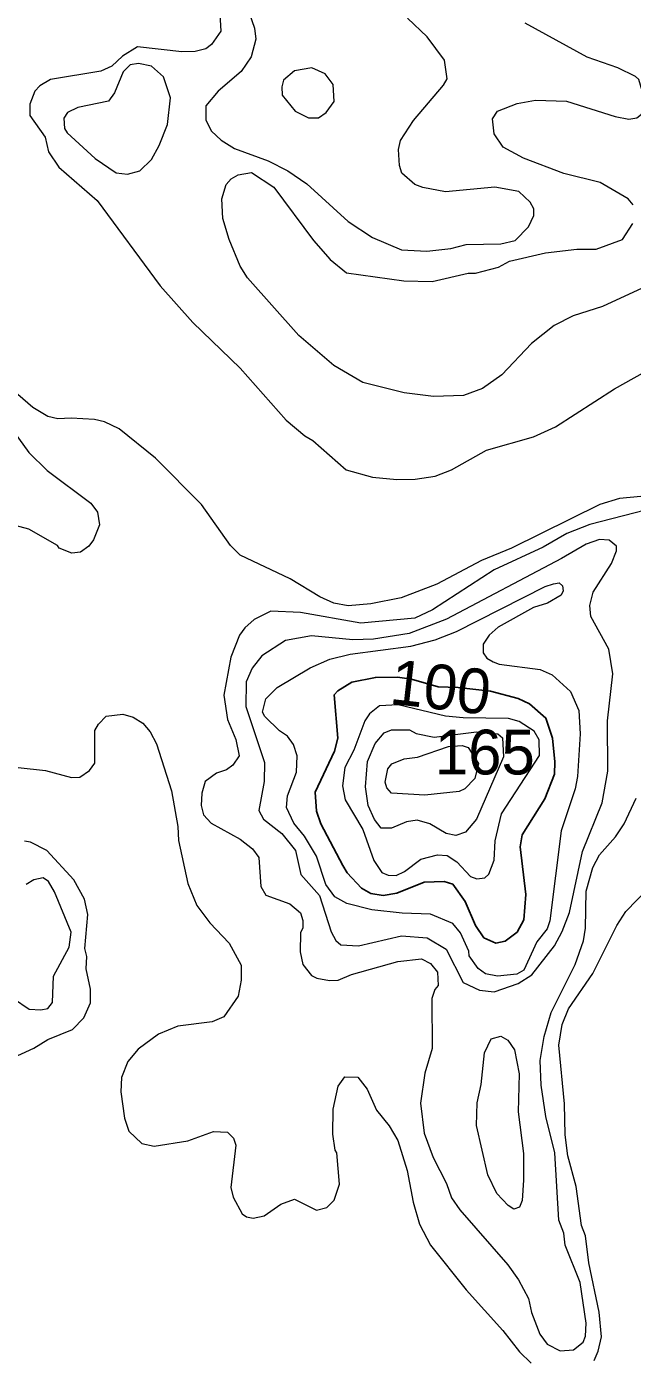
# Model space of a CAD drawing. Extents: x 673.6 to 698.9, y 7012 to 7040.1.
# Drawn here: x 690.749 to 691.831, y 7021.918 to 7024.299 of the extents above; entities that cross this region are included whole.
import ezdxf
from ezdxf.enums import TextEntityAlignment as Align

# ---------------------------------------------------------------- set-up
doc = ezdxf.new("R2010")
doc.units = 0
doc.header["$LTSCALE"] = 0.032
doc.layers.add('1', color=7, linetype='Continuous', lineweight=25)
doc.layers.add('2', color=7, linetype='Continuous', lineweight=13)
doc.layers.add('21', color=7, linetype='Continuous')
doc.layers.add('61', color=7, linetype='Continuous')

msp = doc.modelspace()

# ---------------------------------------------------------------- linework, layer by layer
at = {"layer": '1'}
msp.add_lwpolyline([(691.4117, 7023.1369), (691.4368, 7023.1335), (691.4845, 7023.1197), (691.5202, 7023.1186), (691.5777, 7023.1117), (691.6272, 7023.0987), (691.6472, 7023.0893), (691.6766, 7023.0637), (691.6883, 7023.0278), (691.6929, 7022.9856), (691.692, 7022.9635), (691.6748, 7022.9194), (691.6345, 7022.855), (691.6306, 7022.8336), (691.6411, 7022.7487), (691.6371, 7022.7035), (691.6254, 7022.6812), (691.6042, 7022.6653), (691.5875, 7022.6616), (691.5661, 7022.6708), (691.5507, 7022.693), (691.5325, 7022.7358), (691.5105, 7022.7669), (691.4953, 7022.7715), (691.4591, 7022.7707), (691.4103, 7022.7507), (691.3861, 7022.7469), (691.3639, 7022.7504), (691.3475, 7022.76), (691.3216, 7022.7872), (691.3138, 7022.8001), (691.2747, 7022.875), (691.2671, 7022.8973), (691.2648, 7022.9314), (691.2993, 7023.0049), (691.305, 7023.028), (691.2987, 7023.105), (691.3049, 7023.1123), (691.3301, 7023.1282), (691.3721, 7023.1364)], close=True, dxfattribs=at)
at = {"layer": '2'}
for points in [[(691.0939, 7024.3325), (691.0963, 7024.2913), (691.0794, 7024.2674), (691.0691, 7024.2598), (691.0504, 7024.2548), (691.0266, 7024.254), (690.947, 7024.263), (690.9207, 7024.2465), (690.9011, 7024.2287), (690.8817, 7024.2197), (690.792, 7024.2045), (690.7725, 7024.1934), (690.7636, 7024.1841), (690.7549, 7024.1608), (690.7547, 7024.1406), (690.7822, 7024.1018), (690.788, 7024.0755), (690.8068, 7024.048), (690.8753, 7023.9885), (690.9875, 7023.836), (691.0462, 7023.7708), (691.1306, 7023.6888), (691.2125, 7023.5963), (691.2459, 7023.5682), (691.2607, 7023.5595), (691.3201, 7023.5075), (691.3671, 7023.4944), (691.4106, 7023.4898), (691.4435, 7023.4904), (691.4788, 7023.4958), (691.5081, 7023.5074), (691.5709, 7023.5424), (691.6547, 7023.5665), (691.694, 7023.584), (691.799, 7023.6523), (691.9898, 7023.7589)], [(691.1469, 7024.3241), (691.1563, 7024.2967), (691.1588, 7024.277), (691.1502, 7024.2452), (691.1327, 7024.2189), (691.0912, 7024.1839), (691.0693, 7024.1577), (691.0693, 7024.132), (691.0793, 7024.1124), (691.0964, 7024.0965), (691.1207, 7024.0816), (691.1807, 7024.0597), (691.216, 7024.0413), (691.25, 7024.0181), (691.3234, 7023.9513), (691.3672, 7023.9222), (691.4189, 7023.9006), (691.4639, 7023.8982), (691.5069, 7023.903), (691.5342, 7023.9097), (691.5963, 7023.9113), (691.622, 7023.9169), (691.6459, 7023.9414), (691.6551, 7023.9618), (691.6551, 7023.9734), (691.6487, 7023.9858), (691.6284, 7024.0048), (691.5858, 7024.0123), (691.4975, 7024.0042), (691.457, 7024.0117), (691.4424, 7024.0174), (691.4196, 7024.0373), (691.4152, 7024.051), (691.4136, 7024.0794), (691.4171, 7024.0959), (691.4402, 7024.1314), (691.4939, 7024.1945), (691.5004, 7024.206), (691.4957, 7024.2392), (691.4648, 7024.2808), (691.4293, 7024.3145)], [(691.5841, 7024.1076), (691.5813, 7024.1345), (691.5905, 7024.1481), (691.6257, 7024.1619), (691.6584, 7024.1676), (691.7136, 7024.1661), (691.8002, 7024.1385), (691.8248, 7024.1341), (691.8389, 7024.1364), (691.8477, 7024.1426), (691.8548, 7024.1645), (691.8425, 7024.2046), (691.8367, 7024.2104), (691.8051, 7024.2259), (691.7506, 7024.2449), (691.6397, 7024.3053)], [(691.8236, 7023.9917), (691.7738, 7024.0205), (691.7085, 7024.0368), (691.637, 7024.0641), (691.6003, 7024.0841), (691.5841, 7024.1076)], [(691.8644, 7023.8393), (691.7777, 7023.7993), (691.7255, 7023.7822), (691.6914, 7023.765), (691.6513, 7023.7332), (691.5981, 7023.6768), (691.5635, 7023.6526), (691.5297, 7023.6401), (691.4757, 7023.6386), (691.4238, 7023.645), (691.35, 7023.6633), (691.2981, 7023.6935), (691.2353, 7023.7476), (691.1437, 7023.8506), (691.1307, 7023.8713), (691.1109, 7023.9188), (691.0997, 7023.9562), (691.098, 7023.9918), (691.1055, 7024.0172), (691.1148, 7024.0274), (691.1271, 7024.0345), (691.1509, 7024.0384), (691.1908, 7024.0123), (691.2614, 7023.9173), (691.2912, 7023.8832), (691.3206, 7023.8593), (691.4229, 7023.8451), (691.4734, 7023.844), (691.5377, 7023.8586), (691.5508, 7023.8589), (691.5923, 7023.8694), (691.612, 7023.88), (691.6762, 7023.8948), (691.7321, 7023.9014), (691.7667, 7023.9017), (691.8137, 7023.9191), (691.8319, 7023.9474)], [(691.8325, 7023.9811), (691.8236, 7023.9917)], [(691.5615, 7023.3451), (691.4819, 7023.3029), (691.4182, 7023.2785), (691.3639, 7023.2678), (691.3237, 7023.2646), (691.2982, 7023.2692), (691.273, 7023.2801), (691.2202, 7023.3127), (691.1304, 7023.3546), (691.1131, 7023.3724), (691.0616, 7023.4456), (690.9796, 7023.5283), (690.9142, 7023.5807), (690.8883, 7023.593), (690.8702, 7023.5972), (690.8288, 7023.5999), (690.8051, 7023.5983), (690.7868, 7023.6027), (690.7605, 7023.6186), (690.7333, 7023.6421)], [(690.6972, 7023.615), (690.7533, 7023.5385), (690.7856, 7023.5063), (690.8637, 7023.4478), (690.8758, 7023.4315), (690.8793, 7023.409), (690.8685, 7023.3824), (690.8603, 7023.3712), (690.8455, 7023.3603), (690.83, 7023.3583), (690.8075, 7023.3674), (690.8044, 7023.3722), (690.7529, 7023.401), (690.7158, 7023.4115)], [(691.8728, 7023.467), (691.8463, 7023.4599), (691.8081, 7023.456), (691.7732, 7023.4452), (691.6154, 7023.3672), (691.5615, 7023.3451)], [(691.8549, 7023.4353), (691.7551, 7023.4099), (691.7143, 7023.3936), (691.672, 7023.3691), (691.5842, 7023.3284), (691.474, 7023.257), (691.4428, 7023.2424), (691.3459, 7023.2334), (691.2386, 7023.2523), (691.1853, 7023.2548), (691.1559, 7023.2401), (691.1387, 7023.2248), (691.1293, 7023.2119), (691.1139, 7023.1726), (691.1014, 7023.1047), (691.1078, 7023.0612), (691.1229, 7023.0257), (691.129, 7022.9963), (691.1177, 7022.9796), (691.1064, 7022.9715), (691.0881, 7022.9654), (691.0682, 7022.9506), (691.0619, 7022.9293), (691.0611, 7022.9076)], [(690.7341, 7022.9753), (690.7831, 7022.9703), (690.8294, 7022.9573), (690.8445, 7022.9581), (690.8613, 7022.9703), (690.8711, 7022.9832), (690.8712, 7023.0415), (690.8774, 7023.0529), (690.891, 7023.0672), (690.9209, 7023.0705), (690.9396, 7023.0651), (690.9569, 7023.0547), (690.97, 7023.0391), (690.9813, 7023.018), (691.0078, 7022.9336), (691.019, 7022.8701), (691.0205, 7022.845), (691.0374, 7022.7679), (691.053, 7022.7288), (691.0767, 7022.6976), (691.1109, 7022.6617), (691.1324, 7022.6221), (691.1325, 7022.5954), (691.1273, 7022.5671), (691.1013, 7022.5301)], [(691.0611, 7022.9076), (691.0652, 7022.8909), (691.0791, 7022.876), (691.1306, 7022.8473), (691.1527, 7022.8301), (691.1639, 7022.8148)], [(691.4123, 7022.6286), (691.4546, 7022.6334), (691.4707, 7022.6254), (691.483, 7022.6099), (691.4842, 7022.5861), (691.4784, 7022.5789), (691.4728, 7022.5628), (691.4736, 7022.4731), (691.4604, 7022.4294), (691.453, 7022.3757), (691.4593, 7022.322), (691.4752, 7022.2786), (691.4991, 7022.2321), (691.5084, 7022.2063), (691.5233, 7022.1848), (691.6089, 7022.0865), (691.628, 7022.0599), (691.6454, 7022.0267), (691.651, 7022.0016), (691.6658, 7021.9631), (691.6791, 7021.9451), (691.7023, 7021.9329), (691.7258, 7021.935), (691.7435, 7021.9486), (691.7473, 7021.9596), (691.7489, 7021.9827), (691.7377, 7022.0554), (691.7112, 7022.122), (691.7085, 7022.1434), (691.6996, 7022.1664), (691.6929, 7022.2871), (691.6766, 7022.3521), (691.6684, 7022.408), (691.6667, 7022.4518), (691.6734, 7022.4946), (691.6863, 7022.5378), (691.729, 7022.6233), (691.7438, 7022.666), (691.7472, 7022.6886), (691.7489, 7022.7542), (691.7606, 7022.7969), (691.7726, 7022.8192), (691.8012, 7022.8518), (691.8167, 7022.8749), (691.838, 7022.9206)], [(690.7178, 7022.4536), (690.7623, 7022.4739), (690.7871, 7022.4895), (690.8311, 7022.5074), (690.8516, 7022.5282), (690.8631, 7022.5551), (690.863, 7022.5792), (690.8555, 7022.6158), (690.8565, 7022.6379), (690.8532, 7022.6521), (690.8588, 7022.713), (690.8523, 7022.7403), (690.8334, 7022.7748), (690.7852, 7022.8272), (690.7561, 7022.8422), (690.7456, 7022.8437)], [(691.1639, 7022.8148), (691.1676, 7022.7629), (691.1767, 7022.7473), (691.2196, 7022.7321), (691.2383, 7022.7159), (691.2426, 7022.7021), (691.2427, 7022.6888), (691.2386, 7022.6801), (691.2378, 7022.6463), (691.2427, 7022.6237), (691.2582, 7022.604), (691.2677, 7022.5989), (691.29, 7022.5949), (691.3059, 7022.5957), (691.3294, 7022.6054), (691.4123, 7022.6286)], [(691.7629, 7021.9158), (691.7704, 7021.9324), (691.7758, 7021.9581), (691.7718, 7022.0023), (691.7533, 7022.0906), (691.7472, 7022.1388), (691.7406, 7022.1572), (691.7308, 7022.2268), (691.7161, 7022.2814), (691.7111, 7022.3188), (691.7102, 7022.3745), (691.6996, 7022.4794), (691.7061, 7022.5165), (691.7173, 7022.5441), (691.7603, 7022.6071), (691.8032, 7022.6929), (691.8193, 7022.7179), (691.9229, 7022.825)], [(690.7259, 7022.5626), (690.7536, 7022.5436), (690.7746, 7022.5423), (690.7873, 7022.545), (690.7954, 7022.5553), (690.7973, 7022.6027), (690.8251, 7022.6545), (690.8285, 7022.681), (690.7989, 7022.7534), (690.7885, 7022.772), (690.7788, 7022.7781), (690.762, 7022.7747), (690.7481, 7022.7662)], [(691.1013, 7022.5301), (691.0807, 7022.5211), (691.0191, 7022.5134), (690.9846, 7022.4987), (690.9484, 7022.4722), (690.93, 7022.4499)], [(690.93, 7022.4499), (690.9189, 7022.4214), (690.9172, 7022.3957), (690.9239, 7022.3488), (690.932, 7022.3254), (690.9552, 7022.3036), (690.9769, 7022.299), (691.0372, 7022.3081), (691.0832, 7022.3253), (691.108, 7022.3237), (691.119, 7022.3131), (691.1226, 7022.3008), (691.1138, 7022.2252), (691.1179, 7022.2075), (691.1344, 7022.1781), (691.1419, 7022.1728), (691.154, 7022.1701), (691.1733, 7022.1741), (691.2032, 7022.1954), (691.2275, 7022.2044), (691.2667, 7022.1843), (691.2855, 7022.1891), (691.2987, 7022.2023), (691.3083, 7022.2308), (691.3034, 7022.2872), (691.3003, 7022.2915), (691.2961, 7022.3201), (691.2969, 7022.3652), (691.3057, 7022.4061), (691.3173, 7022.4226), (691.3411, 7022.4222), (691.3573, 7022.4006), (691.3741, 7022.3631), (691.397, 7022.3351), (691.4122, 7022.3091), (691.4287, 7022.2554), (691.4396, 7022.199), (691.4511, 7022.1592), (691.4707, 7022.1217), (691.5344, 7022.0419), (691.6001, 7021.9695), (691.6295, 7021.9311), (691.6505, 7021.9109)]]:
    msp.add_lwpolyline(points, dxfattribs=at)
for points in [[(690.9862, 7024.0866), (691.0011, 7024.1245), (691.0059, 7024.1722), (690.9936, 7024.2095), (690.9725, 7024.2287), (690.9488, 7024.2334), (690.9341, 7024.2309), (690.9217, 7024.2187), (690.9062, 7024.1811), (690.8957, 7024.1661), (690.8407, 7024.1548), (690.8223, 7024.1457), (690.8155, 7024.1358), (690.8167, 7024.1171), (690.8217, 7024.1094), (690.8718, 7024.0636), (690.9093, 7024.0382), (690.9292, 7024.0358), (690.9514, 7024.0418), (690.9724, 7024.0619)], [(691.2985, 7024.1656), (691.2965, 7024.196), (691.2822, 7024.215), (691.2589, 7024.2259), (691.2275, 7024.22), (691.2082, 7024.2038), (691.2049, 7024.1919), (691.2058, 7024.1768), (691.229, 7024.1483), (691.2529, 7024.1364), (691.2706, 7024.1361), (691.284, 7024.1458)], [(691.5583, 7022.5774), (691.5844, 7022.5746), (691.6274, 7022.5892), (691.6515, 7022.6052), (691.6923, 7022.6568), (691.706, 7022.6825), (691.7187, 7022.7163), (691.7421, 7022.8254), (691.7771, 7022.9124), (691.7876, 7022.969), (691.7867, 7023.0588), (691.7965, 7023.1429), (691.7891, 7023.1868), (691.7572, 7023.2455), (691.7555, 7023.265), (691.7612, 7023.2889), (691.7938, 7023.3399), (691.8028, 7023.3625), (691.8027, 7023.3709), (691.7899, 7023.3818), (691.7723, 7023.3829), (691.7485, 7023.3746), (691.7049, 7023.3486), (691.4991, 7023.2407), (691.4326, 7023.215), (691.3687, 7023.2046), (691.3318, 7023.2038), (691.2583, 7023.2104), (691.2115, 7023.2021), (691.1693, 7023.1748), (691.1518, 7023.1529), (691.1412, 7023.1284), (691.1406, 7023.0846), (691.1743, 7022.9843), (691.1736, 7022.9504), (691.164, 7022.8984), (691.1722, 7022.8831), (691.2051, 7022.8576), (691.2292, 7022.8274), (691.239, 7022.7844), (691.2722, 7022.7468), (691.293, 7022.6816), (691.3015, 7022.6666), (691.3102, 7022.6584), (691.3419, 7022.6566), (691.4189, 7022.6746), (691.4644, 7022.6712), (691.4984, 7022.651), (691.529, 7022.5912)], [(691.5397, 7022.6392), (691.5392, 7022.647), (691.524, 7022.6801), (691.5108, 7022.6964), (691.4708, 7022.7132), (691.4198, 7022.7149), (691.3656, 7022.7214), (691.3209, 7022.7324), (691.2997, 7022.7444), (691.2836, 7022.7664), (691.2667, 7022.8171), (691.2455, 7022.8526), (691.2263, 7022.8759), (691.2132, 7022.9042), (691.2152, 7022.9246), (691.2311, 7022.9672), (691.2326, 7022.9963), (691.2261, 7023.0167), (691.2149, 7023.0317), (691.2006, 7023.041), (691.1745, 7023.0663), (691.1705, 7023.0744), (691.1764, 7023.0981), (691.1969, 7023.1185), (691.2554, 7023.1534), (691.2909, 7023.1689), (691.3274, 7023.1782), (691.4357, 7023.1924), (691.4788, 7023.2033), (691.5168, 7023.2184), (691.6754, 7023.2989), (691.6906, 7023.3039), (691.7004, 7023.3052), (691.7063, 7023.3), (691.7075, 7023.2913), (691.7042, 7023.2836), (691.6798, 7023.2688), (691.6548, 7023.2612), (691.5917, 7023.2263), (691.5753, 7023.212), (691.5648, 7023.1956), (691.5649, 7023.1801), (691.5714, 7023.171), (691.5824, 7023.1642), (691.5931, 7023.1602), (691.6663, 7023.1504), (691.6882, 7023.1412), (691.7209, 7023.1115), (691.7357, 7023.0772), (691.7382, 7023.0356), (691.7333, 7022.9596), (691.729, 7022.9372), (691.7042, 7022.8624), (691.684, 7022.7012), (691.6791, 7022.6871), (691.6607, 7022.664), (691.6372, 7022.6135), (691.6247, 7022.6062), (691.5903, 7022.6023), (691.5688, 7022.6069), (691.5556, 7022.6164)], [(691.5972, 7022.8928), (691.6656, 7022.9971), (691.665, 7023.0251), (691.6559, 7023.0402), (691.6292, 7023.0574), (691.6098, 7023.0631), (691.529, 7023.0641), (691.4974, 7023.0673), (691.4131, 7023.0873), (691.3794, 7023.0855), (691.3614, 7023.0712), (691.3531, 7023.0591), (691.3338, 7023.0066), (691.3176, 7022.9756), (691.3134, 7022.9424), (691.3183, 7022.9179), (691.3498, 7022.8646), (691.3692, 7022.8095), (691.3834, 7022.7877), (691.3947, 7022.7831), (691.409, 7022.7827), (691.4239, 7022.7895), (691.4532, 7022.8114), (691.483, 7022.8192), (691.5005, 7022.8179), (691.5174, 7022.8066), (691.5418, 7022.7806), (691.5532, 7022.7765), (691.5677, 7022.7782), (691.5748, 7022.785), (691.5846, 7022.8097), (691.5862, 7022.8442)], [(691.5526, 7022.8832), (691.5334, 7022.8601), (691.5159, 7022.8538), (691.4984, 7022.8573), (691.4694, 7022.875), (691.4465, 7022.8816), (691.4276, 7022.8786), (691.401, 7022.867), (691.3827, 7022.8668), (691.3703, 7022.8823), (691.3594, 7022.9077), (691.3545, 7022.9409), (691.3579, 7022.9859), (691.3719, 7023.0183), (691.3879, 7023.0374), (691.4008, 7023.0428), (691.433, 7023.0428), (691.4448, 7023.0362), (691.4773, 7023.0296), (691.5525, 7023.0394), (691.5908, 7023.0353), (691.5992, 7023.0283), (691.6008, 7022.9947)], [(691.5562, 7022.9824), (691.5497, 7022.9559), (691.5318, 7022.9371), (691.522, 7022.9325), (691.4604, 7022.9261), (691.401, 7022.9296), (691.3927, 7022.9389), (691.3898, 7022.9493), (691.3944, 7022.9729), (691.4016, 7022.9821), (691.4234, 7022.9909), (691.4476, 7022.9938), (691.5027, 7023.0132), (691.5271, 7023.0148), (691.5376, 7023.0114)], [(691.5964, 7022.4954), (691.6087, 7022.4884), (691.6206, 7022.4712), (691.6288, 7022.428), (691.6273, 7022.3599), (691.637, 7022.2857), (691.637, 7022.2383), (691.6346, 7022.202), (691.6294, 7022.1897), (691.6196, 7022.1865), (691.6092, 7022.1928), (691.589, 7022.2141), (691.5728, 7022.2475), (691.5525, 7022.3357), (691.5539, 7022.376), (691.5613, 7022.4092), (691.5672, 7022.4655), (691.5791, 7022.4908)]]:
    msp.add_lwpolyline(points, close=True, dxfattribs=at)

# ---------------------------------------------------------------- texts
at = {"layer": '21'}
msp.add_text('165', height=0.08, dxfattribs=at).set_placement((691.4784, 7022.963))
at = {"layer": '61'}
msp.add_text('100', height=0.08, rotation=353.446, dxfattribs=at).set_placement((691.4844, 7023.0795), align=Align.CENTER)

doc.saveas('drawing.dxf')
